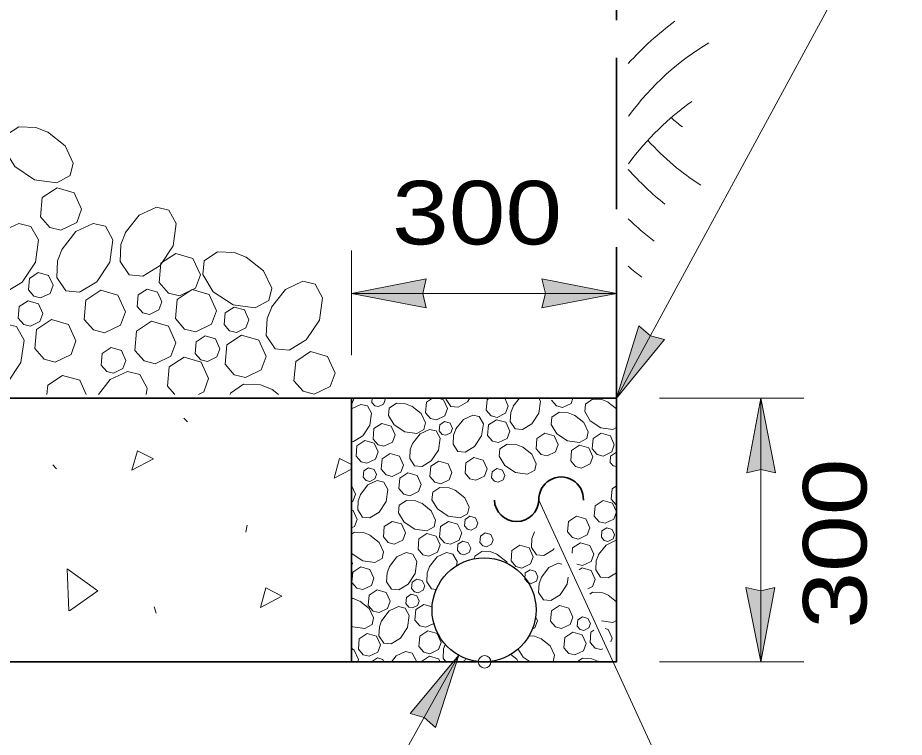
# Model space of a CAD drawing. Extents: x 17672 to 18472, y -9785 to -9267.
# Drawn here: x 18130.28 to 18179.55, y -9409.42 to -9369.46 of the extents above; entities that cross this region are included whole.
import ezdxf

# ---------------------------------------------------------------- set-up
doc = ezdxf.new("R2010")
doc.units = 0
doc.header["$LTSCALE"] = 1.4
doc.header["$PDMODE"] = 32
doc.header["$PDSIZE"] = 0.7
doc.linetypes.add('LONG_DASHED', pattern=[7.5, 6, -1.5])
for name, color, linetype, lineweight in [('1', 7, 'Continuous', 13), ('15', 7, 'Continuous', 13), ('16', 7, 'Continuous', 13)]:
    doc.layers.add(name, color=color, linetype=linetype, lineweight=lineweight)
doc.layers.add('19', color=7, linetype='Continuous')

msp = doc.modelspace()

# ---------------------------------------------------------------- hatches: boundary and pattern name
at = {"layer": '16'}
for points in [[(18148.839, -9384.78), (18152.979, -9385.562), (18152.79, -9384.78), (18152.977, -9383.962)], [(18163.555, -9384.78), (18159.418, -9385.562), (18159.604, -9384.78), (18159.415, -9383.959)], [(18163.555, -9390.594), (18166.217, -9387.329), (18165.44, -9387.121), (18164.808, -9386.567)], [(18171.575, -9390.594), (18170.793, -9394.732), (18171.575, -9394.545), (18172.396, -9394.734)], [(18171.575, -9405.234), (18172.357, -9401.097), (18171.575, -9401.283), (18170.754, -9401.097)], [(18154.79, -9404.869), (18152.092, -9408.102), (18152.866, -9408.32), (18153.491, -9408.884)]]:
    msp.add_hatch(color=256, dxfattribs=at).paths.add_polyline_path(points)

# ---------------------------------------------------------------- linework, layer by layer
at = {"layer": '1', "linetype": 'LONG_DASHED', "lineweight": 35}
msp.add_line((18163.555, -9390.594), (18163.555, -9317.655), dxfattribs=at)
at = {"layer": '1'}
for p, q in [((18139.01, -9390.38), (18138.61, -9389.921)), ((18144.428, -9390.101), (18144.782, -9390.38)), ((18149.962, -9390.82), (18149.984, -9390.594)), ((18157.815, -9391.038), (18158.165, -9390.594)), ((18163.085, -9390.805), (18163.555, -9391.178)), ((18139.511, -9391.705), (18139.719, -9391.906)), ((18132.236, -9394.293), (18132.447, -9394.506)), ((18148.839, -9394.531), (18147.874, -9395.038)), ((18142.952, -9398.028), (18143.038, -9397.633)), ((18163.087, -9401.523), (18163.555, -9401.893)), ((18137.869, -9402.175), (18137.979, -9402.533))]:
    msp.add_line(p, q, dxfattribs=at)
at = {"layer": '1', "lineweight": 25}
msp.add_line((18162.533, -9405.192), (18162.585, -9405.234), dxfattribs=at)
at = {"layer": '1'}
for points in [[(18131.943, -9375.802), (18132.918, -9376.574), (18133.369, -9377.539), (18133.206, -9378.216), (18132.452, -9378.633), (18131.221, -9378.459), (18130.116, -9377.729), (18129.542, -9376.774), (18129.614, -9376.006), (18130.354, -9375.511), (18131.297, -9375.555), (18131.992, -9375.827)], [(18131.552, -9380.519), (18131.647, -9379.448), (18132.474, -9378.906), (18133.423, -9379.179), (18133.835, -9380.092), (18133.561, -9380.835), (18132.682, -9381.261), (18132.063, -9381.106), (18131.553, -9380.518)], [(18136.264, -9381.402), (18137.036, -9380.427), (18138.002, -9379.975), (18138.679, -9380.138), (18139.096, -9380.893), (18138.922, -9382.123), (18138.192, -9383.228), (18137.236, -9383.803), (18136.469, -9383.73), (18135.973, -9382.99), (18136.018, -9382.048), (18136.29, -9381.353)], [(18128.607, -9382.311), (18129.379, -9381.337), (18130.345, -9380.885), (18131.021, -9381.048), (18131.438, -9381.803), (18131.265, -9383.034), (18130.535, -9384.138), (18129.579, -9384.713), (18128.812, -9384.641), (18128.316, -9383.9), (18128.36, -9382.958), (18128.633, -9382.262)], [(18132.745, -9382.307), (18133.517, -9381.332), (18134.483, -9380.88), (18135.16, -9381.044), (18135.577, -9381.798), (18135.403, -9383.029), (18134.674, -9384.133), (18133.718, -9384.708), (18132.95, -9384.636), (18132.455, -9383.895), (18132.498, -9382.953), (18132.771, -9382.258)], [(18138.148, -9384.17), (18138.244, -9383.099), (18139.07, -9382.557), (18140.02, -9382.83), (18140.432, -9383.743), (18140.158, -9384.486), (18139.279, -9384.912), (18138.659, -9384.756), (18138.149, -9384.169)], [(18142.973, -9382.749), (18143.948, -9383.521), (18144.4, -9384.487), (18144.236, -9385.164), (18143.482, -9385.58), (18142.251, -9385.407), (18141.147, -9384.678), (18140.572, -9383.721), (18140.644, -9382.955), (18141.384, -9382.459), (18142.327, -9382.502), (18143.022, -9382.775)], [(18139.047, -9386.169), (18139.143, -9385.099), (18139.969, -9384.557), (18140.918, -9384.83), (18141.33, -9385.742), (18141.056, -9386.486), (18140.177, -9386.912), (18139.558, -9386.756), (18139.048, -9386.169)], [(18144.39, -9385.525), (18145.162, -9384.55), (18146.127, -9384.099), (18146.804, -9384.262), (18147.221, -9385.016), (18147.048, -9386.247), (18146.318, -9387.352), (18145.362, -9387.927), (18144.595, -9387.854), (18144.099, -9387.114), (18144.143, -9386.171), (18144.415, -9385.476)], [(18133.981, -9386.212), (18134.077, -9385.142), (18134.903, -9384.599), (18135.852, -9384.872), (18136.265, -9385.785), (18135.991, -9386.529), (18135.111, -9386.954), (18134.492, -9386.799), (18133.982, -9386.211)], [(18130.308, -9386.143), (18130.366, -9385.501), (18130.861, -9385.176), (18131.431, -9385.34), (18131.678, -9385.887), (18131.514, -9386.334), (18130.986, -9386.589), (18130.615, -9386.496), (18130.309, -9386.143)], [(18141.754, -9386.493), (18141.811, -9385.851), (18142.307, -9385.526), (18142.877, -9385.69), (18143.125, -9386.237), (18142.96, -9386.684), (18142.433, -9386.939), (18142.061, -9386.846), (18141.755, -9386.493)], [(18127.805, -9387.878), (18128.577, -9386.903), (18129.543, -9386.452), (18130.219, -9386.615), (18130.636, -9387.369), (18130.462, -9388.6), (18129.733, -9389.704), (18128.777, -9390.279), (18128.01, -9390.207), (18127.514, -9389.467), (18127.558, -9388.524), (18127.831, -9387.829)], [(18131.238, -9387.837), (18131.334, -9386.767), (18132.16, -9386.224), (18133.109, -9386.497), (18133.522, -9387.411), (18133.247, -9388.154), (18132.368, -9388.58), (18131.749, -9388.424), (18131.239, -9387.837)], [(18140.146, -9388.103), (18140.203, -9387.46), (18140.699, -9387.135), (18141.268, -9387.299), (18141.516, -9387.846), (18141.351, -9388.293), (18140.824, -9388.549), (18140.453, -9388.455), (18140.146, -9388.102)], [(18134.923, -9388.748), (18134.98, -9388.106), (18135.476, -9387.78), (18136.046, -9387.944), (18136.293, -9388.492), (18136.129, -9388.938), (18135.601, -9389.194), (18135.23, -9389.1), (18134.924, -9388.748)], [(18145.635, -9389.617), (18145.731, -9388.548), (18146.557, -9388.005), (18147.506, -9388.278), (18147.918, -9389.191), (18147.644, -9389.935), (18146.765, -9390.36), (18146.147, -9390.204), (18145.636, -9389.618)], [(18138.61, -9389.921), (18138.705, -9388.85), (18139.532, -9388.309), (18140.481, -9388.582), (18140.893, -9389.494), (18140.619, -9390.238), (18140.324, -9390.38)], [(18131.907, -9390.38), (18131.953, -9389.865), (18132.778, -9389.323), (18133.729, -9389.596), (18134.083, -9390.38)], [(18134.769, -9390.38), (18135.42, -9389.558), (18136.386, -9389.106), (18137.063, -9389.27), (18137.48, -9390.024), (18137.429, -9390.38)], [(18142.092, -9390.38), (18142.1, -9390.305), (18142.839, -9389.81), (18143.782, -9389.853), (18144.478, -9390.126)], [(18148.974, -9390.594), (18148.856, -9390.908), (18148.839, -9390.918)], [(18148.839, -9391.173), (18149.354, -9390.932), (18149.719, -9391.021), (18149.945, -9391.425), (18149.849, -9392.089), (18149.457, -9392.685), (18148.942, -9392.994), (18148.839, -9392.984)], [(18150.663, -9390.594), (18150.702, -9390.682), (18150.614, -9390.923), (18150.33, -9391.06), (18150.129, -9391.008), (18149.962, -9390.82)], [(18152.18, -9391.028), (18152.705, -9391.445), (18152.95, -9391.967), (18152.861, -9392.332), (18152.455, -9392.555), (18151.79, -9392.462), (18151.195, -9392.07), (18150.886, -9391.553), (18150.925, -9391.141), (18151.325, -9390.874), (18151.832, -9390.896), (18152.205, -9391.043)], [(18152.945, -9391.396), (18152.996, -9390.817), (18153.339, -9390.594)], [(18153.675, -9390.594), (18153.952, -9390.673), (18154.173, -9391.165), (18154.026, -9391.567), (18153.553, -9391.795), (18153.219, -9391.712), (18152.945, -9391.396)], [(18155.408, -9390.594), (18155.281, -9390.785), (18154.766, -9391.097), (18154.352, -9391.057), (18154.084, -9390.658), (18154.087, -9390.594)], [(18156.31, -9391.256), (18156.364, -9390.678), (18156.491, -9390.594)], [(18157.347, -9390.594), (18157.54, -9391.026), (18157.393, -9391.425), (18156.92, -9391.656), (18156.587, -9391.57), (18156.31, -9391.256)], [(18159.246, -9390.594), (18159.339, -9390.763), (18159.246, -9391.425), (18158.854, -9392.021), (18158.339, -9392.332), (18157.925, -9392.293), (18157.658, -9391.893), (18157.683, -9391.386), (18157.83, -9391.011)], [(18161.136, -9390.594), (18161.033, -9390.879), (18160.558, -9391.109), (18160.224, -9391.023), (18159.95, -9390.707)], [(18163.555, -9392.222), (18163.359, -9392.33), (18162.695, -9392.236), (18162.099, -9391.844), (18161.79, -9391.33), (18161.83, -9390.915), (18162.229, -9390.648), (18162.736, -9390.67), (18163.109, -9390.817)], [(18161.224, -9391.531), (18161.749, -9391.947), (18161.991, -9392.464), (18161.906, -9392.83), (18161.496, -9393.055), (18160.835, -9392.962), (18160.239, -9392.567), (18159.93, -9392.053), (18159.969, -9391.641), (18160.366, -9391.374), (18160.876, -9391.398), (18161.251, -9391.543)], [(18154.633, -9392.293), (18155.05, -9391.768), (18155.57, -9391.526), (18155.935, -9391.614), (18156.16, -9392.018), (18156.065, -9392.682), (18155.673, -9393.278), (18155.158, -9393.587), (18154.744, -9393.548), (18154.477, -9393.148), (18154.501, -9392.641), (18154.648, -9392.266)], [(18152.232, -9393.092), (18152.646, -9392.565), (18153.165, -9392.322), (18153.531, -9392.41), (18153.756, -9392.817), (18153.663, -9393.479), (18153.268, -9394.075), (18152.754, -9394.383), (18152.339, -9394.344), (18152.072, -9393.947), (18152.097, -9393.44), (18152.244, -9393.065)], [(18149.084, -9393.805), (18149.136, -9393.227), (18149.582, -9392.935), (18150.092, -9393.082), (18150.315, -9393.575), (18150.168, -9393.974), (18149.692, -9394.205), (18149.361, -9394.119), (18149.084, -9393.803)], [(18159.087, -9393.401), (18159.138, -9392.825), (18159.585, -9392.531), (18160.097, -9392.68), (18160.317, -9393.17), (18160.17, -9393.57), (18159.697, -9393.8), (18159.364, -9393.717), (18159.089, -9393.401)], [(18162.21, -9393.406), (18162.261, -9392.827), (18162.705, -9392.535), (18163.217, -9392.682), (18163.437, -9393.173), (18163.29, -9393.575), (18162.817, -9393.803), (18162.484, -9393.719), (18162.21, -9393.403)], [(18158.334, -9393.29), (18158.859, -9393.707), (18159.102, -9394.227), (18159.013, -9394.592), (18158.609, -9394.815), (18157.945, -9394.724), (18157.352, -9394.33), (18157.04, -9393.815), (18157.08, -9393.401), (18157.479, -9393.136), (18157.986, -9393.158), (18158.361, -9393.305)], [(18163.202, -9394.153), (18163.232, -9393.807), (18163.499, -9393.631), (18163.555, -9393.648)], [(18147.874, -9395.038), (18148.17, -9393.947), (18148.839, -9394.281)], [(18163.555, -9394.391), (18163.366, -9394.342), (18163.202, -9394.153)], [(18149.332, -9395.935), (18149.746, -9395.41), (18150.266, -9395.168), (18150.631, -9395.256), (18150.856, -9395.663), (18150.761, -9396.325), (18150.371, -9396.92), (18149.854, -9397.229), (18149.442, -9397.19), (18149.175, -9396.793), (18149.197, -9396.283), (18149.344, -9395.908)], [(18148.839, -9395.437), (18149.057, -9395.923), (18148.91, -9396.325), (18148.839, -9396.359)], [(18154.599, -9395.702), (18155.124, -9396.119), (18155.366, -9396.638), (18155.278, -9397.004), (18154.874, -9397.229), (18154.209, -9397.133), (18153.616, -9396.741), (18153.305, -9396.227), (18153.344, -9395.812), (18153.744, -9395.548), (18154.251, -9395.57), (18154.626, -9395.717)], [(18163.266, -9396.192), (18163.317, -9395.616), (18163.555, -9395.459)], [(18152.739, -9396.428), (18153.263, -9396.844), (18153.506, -9397.364), (18153.42, -9397.729), (18153.013, -9397.952), (18152.349, -9397.859), (18151.756, -9397.467), (18151.445, -9396.952), (18151.484, -9396.538), (18151.883, -9396.273), (18152.391, -9396.295), (18152.766, -9396.442)], [(18163.555, -9396.511), (18163.54, -9396.506), (18163.266, -9396.192)], [(18148.839, -9396.808), (18148.92, -9396.83), (18149.141, -9397.322), (18148.994, -9397.722), (18148.839, -9397.798)], [(18148.839, -9398.138), (18148.994, -9398.033), (18149.501, -9398.058), (18149.876, -9398.205)], [(18149.849, -9398.19), (18150.374, -9398.604), (18150.619, -9399.126), (18150.531, -9399.489), (18150.124, -9399.714), (18149.459, -9399.621), (18148.866, -9399.229), (18148.839, -9399.183)], [(18160.089, -9398.935), (18160.033, -9399.018), (18159.518, -9399.33), (18159.104, -9399.29), (18158.837, -9398.891), (18158.861, -9398.384), (18159.009, -9398.008)], [(18161.089, -9399.202), (18161.116, -9398.91), (18161.56, -9398.619), (18162.072, -9398.766), (18162.295, -9399.256), (18162.146, -9399.658), (18161.673, -9399.886), (18161.354, -9399.808)], [(18162.567, -9399.271), (18162.984, -9398.744), (18163.504, -9398.501), (18163.555, -9398.513)], [(18150.942, -9399.935), (18151.356, -9399.41), (18151.879, -9399.168), (18152.244, -9399.254), (18152.467, -9399.66), (18152.374, -9400.325), (18151.982, -9400.918), (18151.467, -9401.229), (18151.053, -9401.19), (18150.785, -9400.79), (18150.81, -9400.283), (18150.957, -9399.908)], [(18153.17, -9399.933), (18153.587, -9399.408), (18154.107, -9399.165), (18154.472, -9399.251), (18154.697, -9399.658), (18154.663, -9399.896)], [(18155.665, -9399.506), (18155.678, -9399.371), (18156.077, -9399.104), (18156.584, -9399.129), (18156.959, -9399.276)], [(18156.933, -9399.263), (18157.457, -9399.678), (18157.499, -9399.766)], [(18163.555, -9400.285), (18163.092, -9400.562), (18162.678, -9400.523), (18162.411, -9400.126), (18162.435, -9399.619), (18162.582, -9399.244)], [(18159.386, -9400.526), (18159.803, -9400.001), (18160.322, -9399.756), (18160.513, -9399.803)], [(18133.131, -9402.398), (18133.035, -9400.06), (18134.741, -9401.281), (18133.163, -9402.393)], [(18153.54, -9401.212), (18153.283, -9401.187), (18153.016, -9400.788), (18153.038, -9400.281), (18153.185, -9399.906)], [(18158.457, -9400.641), (18158.489, -9400.295), (18158.756, -9400.119), (18159.062, -9400.207), (18159.195, -9400.504), (18159.107, -9400.744), (18158.822, -9400.881), (18158.624, -9400.83), (18158.459, -9400.641)], [(18161.491, -9400.116), (18161.646, -9400.016), (18162.156, -9400.163), (18162.379, -9400.656), (18162.232, -9401.055), (18161.96, -9401.187)], [(18160.871, -9400.538), (18160.817, -9400.915), (18160.425, -9401.511), (18159.91, -9401.82), (18159.496, -9401.781), (18159.232, -9401.381), (18159.254, -9400.874), (18159.401, -9400.499)], [(18148.839, -9401.719), (18148.947, -9401.724), (18149.32, -9401.874)], [(18162.082, -9401.467), (18162.232, -9401.366), (18162.739, -9401.391), (18163.114, -9401.538)], [(18149.293, -9401.859), (18149.82, -9402.273), (18150.062, -9402.795), (18149.974, -9403.16), (18149.57, -9403.384), (18148.905, -9403.29), (18148.839, -9403.246)], [(18150.511, -9402.933), (18150.925, -9402.408), (18151.447, -9402.165), (18151.81, -9402.254), (18152.035, -9402.66), (18151.942, -9403.322), (18151.55, -9403.918), (18151.033, -9404.227), (18150.621, -9404.187), (18150.354, -9403.79), (18150.379, -9403.281), (18150.526, -9402.908)], [(18152.359, -9402.91), (18152.41, -9402.335), (18152.857, -9402.043), (18153.312, -9402.175)], [(18159.062, -9402.714), (18159.168, -9402.95), (18159.021, -9403.352), (18158.879, -9403.42)], [(18153.408, -9403.099), (18152.969, -9403.312), (18152.636, -9403.227), (18152.359, -9402.91)], [(18163.555, -9402.942), (18163.361, -9403.048), (18162.734, -9402.96)], [(18149.212, -9404.526), (18149.263, -9403.95), (18149.709, -9403.658), (18150.222, -9403.803), (18150.442, -9404.295), (18150.295, -9404.695), (18149.822, -9404.925), (18149.489, -9404.842), (18149.214, -9404.526)], [(18158.7, -9403.788), (18159.004, -9403.803), (18159.379, -9403.95)], [(18160.634, -9404.452), (18160.687, -9403.876), (18161.131, -9403.582), (18161.643, -9403.732), (18161.866, -9404.222), (18161.717, -9404.621), (18161.244, -9404.852), (18160.91, -9404.768), (18160.636, -9404.452)], [(18162.089, -9404.156), (18162.141, -9403.58), (18162.3, -9403.474)], [(18162.92, -9403.384), (18163.097, -9403.433), (18163.317, -9403.925), (18163.244, -9404.126)], [(18154.067, -9405.234), (18153.928, -9405.023), (18153.95, -9404.516), (18154.045, -9404.273)], [(18159.352, -9403.935), (18159.879, -9404.352), (18160.121, -9404.871), (18160.033, -9405.234)], [(18162.803, -9404.506), (18162.697, -9404.555), (18162.364, -9404.472), (18162.089, -9404.156)], [(18148.839, -9404.469), (18148.974, -9404.577), (18149.217, -9405.097), (18149.182, -9405.234)], [(18151.053, -9405.234), (18151.317, -9404.898), (18151.839, -9404.656), (18152.205, -9404.744), (18152.428, -9405.151), (18152.415, -9405.234)], [(18158.763, -9405.234), (18158.369, -9404.974), (18158.097, -9404.521)], [(18150.001, -9405.234), (18150.004, -9405.192), (18150.271, -9405.018), (18150.577, -9405.107), (18150.636, -9405.234)], [(18152.712, -9405.234), (18152.717, -9405.207), (18153.16, -9404.915), (18153.673, -9405.062), (18153.751, -9405.234)], [(18155.187, -9405.053), (18155.124, -9405.153), (18154.986, -9405.234)], [(18157.692, -9404.817), (18158.018, -9405.077), (18158.092, -9405.234)], [(18161.379, -9405.234), (18161.675, -9405.036), (18162.183, -9405.06), (18162.558, -9405.207)]]:
    msp.add_lwpolyline(points, dxfattribs=at)
for points in [[(18130.876, -9384.577), (18130.933, -9383.935), (18131.429, -9383.61), (18131.999, -9383.774), (18132.246, -9384.321), (18132.082, -9384.768), (18131.554, -9385.023), (18131.183, -9384.93)], [(18136.928, -9385.497), (18136.985, -9384.855), (18137.481, -9384.53), (18138.051, -9384.694), (18138.298, -9385.241), (18138.134, -9385.687), (18137.606, -9385.943), (18137.235, -9385.85)], [(18136.791, -9387.932), (18136.886, -9386.862), (18137.713, -9386.32), (18138.662, -9386.593), (18139.074, -9387.506), (18138.8, -9388.25), (18137.921, -9388.676), (18137.302, -9388.52)], [(18141.805, -9388.698), (18141.9, -9387.628), (18142.727, -9387.086), (18143.676, -9387.359), (18144.088, -9388.271), (18143.814, -9389.015), (18142.935, -9389.441), (18142.316, -9389.285)], [(18153.705, -9392.408), (18153.736, -9392.062), (18154.004, -9391.888), (18154.31, -9391.977), (18154.442, -9392.271), (18154.354, -9392.511), (18154.07, -9392.648), (18153.869, -9392.599)], [(18156.396, -9392.653), (18156.447, -9392.077), (18156.891, -9391.783), (18157.403, -9391.93), (18157.626, -9392.423), (18157.477, -9392.825), (18157.004, -9393.053), (18156.67, -9392.969)], [(18150.028, -9392.859), (18150.08, -9392.281), (18150.526, -9391.989), (18151.038, -9392.136), (18151.258, -9392.629), (18151.111, -9393.028), (18150.638, -9393.258), (18150.305, -9393.173)], [(18161.013, -9394.07), (18161.065, -9393.494), (18161.511, -9393.202), (18162.021, -9393.349), (18162.241, -9393.842), (18162.097, -9394.241), (18161.621, -9394.472), (18161.288, -9394.386)], [(18136.626, -9394.587), (18136.94, -9393.511), (18137.834, -9393.964)], [(18150.484, -9394.535), (18150.535, -9393.959), (18150.981, -9393.668), (18151.491, -9393.812), (18151.714, -9394.305), (18151.567, -9394.707), (18151.094, -9394.935), (18150.761, -9394.852)], [(18155.141, -9394.749), (18155.192, -9394.173), (18155.638, -9393.881), (18156.148, -9394.028), (18156.371, -9394.518), (18156.224, -9394.92), (18155.749, -9395.148), (18155.415, -9395.065)], [(18153.187, -9394.947), (18153.236, -9394.371), (18153.682, -9394.08), (18154.195, -9394.227), (18154.415, -9394.717), (18154.268, -9395.119), (18153.795, -9395.349), (18153.462, -9395.263)], [(18149.479, -9394.974), (18149.511, -9394.629), (18149.776, -9394.455), (18150.084, -9394.543), (18150.217, -9394.837), (18150.129, -9395.077), (18149.844, -9395.214), (18149.643, -9395.165)], [(18151.464, -9395.607), (18151.516, -9395.031), (18151.962, -9394.739), (18152.474, -9394.883), (18152.695, -9395.376), (18152.548, -9395.776), (18152.075, -9396.006), (18151.741, -9395.923)], [(18156.616, -9395.016), (18156.648, -9394.673), (18156.915, -9394.496), (18157.222, -9394.584), (18157.354, -9394.879), (18157.266, -9395.119), (18156.982, -9395.258), (18156.781, -9395.207)], [(18162.322, -9397.138), (18162.374, -9396.56), (18162.817, -9396.271), (18163.33, -9396.415), (18163.553, -9396.908), (18163.403, -9397.308), (18162.93, -9397.538), (18162.597, -9397.455)], [(18155.109, -9397.673), (18155.141, -9397.325), (18155.408, -9397.151), (18155.714, -9397.239), (18155.847, -9397.533), (18155.758, -9397.773), (18155.474, -9397.913), (18155.273, -9397.861)], [(18160.844, -9398.013), (18160.896, -9397.437), (18161.342, -9397.143), (18161.852, -9397.293), (18162.075, -9397.783), (18161.928, -9398.185), (18161.452, -9398.413), (18161.119, -9398.33)], [(18150.604, -9398.298), (18150.656, -9397.722), (18151.099, -9397.43), (18151.611, -9397.577), (18151.832, -9398.067), (18151.685, -9398.469), (18151.212, -9398.7), (18150.879, -9398.614)], [(18153.724, -9398.303), (18153.776, -9397.724), (18154.222, -9397.435), (18154.732, -9397.58), (18154.955, -9398.072), (18154.808, -9398.472), (18154.332, -9398.702), (18153.999, -9398.619)], [(18162.717, -9398.308), (18162.746, -9397.962), (18163.013, -9397.788), (18163.32, -9397.876), (18163.455, -9398.17), (18163.366, -9398.41), (18163.082, -9398.548), (18162.881, -9398.499)], [(18152.528, -9398.969), (18152.58, -9398.393), (18153.026, -9398.102), (18153.535, -9398.249), (18153.758, -9398.739), (18153.611, -9399.141), (18153.138, -9399.369), (18152.803, -9399.285)], [(18155.969, -9398.599), (18155.999, -9398.254), (18156.266, -9398.077), (18156.575, -9398.165), (18156.707, -9398.462), (18156.619, -9398.702), (18156.334, -9398.839), (18156.136, -9398.788)], [(18154.717, -9399.053), (18154.746, -9398.705), (18155.013, -9398.531), (18155.322, -9398.619), (18155.455, -9398.913), (18155.366, -9399.156), (18155.082, -9399.293), (18154.881, -9399.241)], [(18157.697, -9399.626), (18157.749, -9399.05), (18158.195, -9398.759), (18158.705, -9398.906), (18158.928, -9399.398), (18158.778, -9399.798), (18158.305, -9400.028), (18157.972, -9399.942)], [(18148.852, -9400.82), (18148.903, -9400.244), (18149.347, -9399.955), (18149.859, -9400.099), (18150.082, -9400.592), (18149.935, -9400.991), (18149.459, -9401.222), (18149.126, -9401.136)], [(18152.165, -9401.156), (18152.195, -9400.81), (18152.462, -9400.634), (18152.768, -9400.722), (18152.903, -9401.018), (18152.815, -9401.259), (18152.531, -9401.396), (18152.33, -9401.347)], [(18143.768, -9402.219), (18144.065, -9401.131), (18144.962, -9401.585)], [(18149.758, -9402.097), (18149.81, -9401.521), (18150.256, -9401.229), (18150.766, -9401.376), (18150.989, -9401.866), (18150.842, -9402.266), (18150.369, -9402.496), (18150.033, -9402.413)], [(18151.859, -9401.999), (18151.888, -9401.653), (18152.156, -9401.479), (18152.462, -9401.567), (18152.597, -9401.861), (18152.508, -9402.102), (18152.224, -9402.239), (18152.023, -9402.19)], [(18159.893, -9402.982), (18159.945, -9402.403), (18160.391, -9402.111), (18160.903, -9402.259), (18161.124, -9402.751), (18160.977, -9403.153), (18160.504, -9403.381), (18160.17, -9403.298)], [(18161.369, -9403.249), (18161.401, -9402.903), (18161.668, -9402.729), (18161.974, -9402.817), (18162.107, -9403.111), (18162.018, -9403.352), (18161.734, -9403.489), (18161.535, -9403.44)], [(18152.58, -9404.386), (18152.631, -9403.808), (18153.077, -9403.516), (18153.587, -9403.663), (18153.81, -9404.156), (18153.663, -9404.555), (18153.19, -9404.786), (18152.854, -9404.702)]]:
    msp.add_lwpolyline(points, close=True, dxfattribs=at)
at = {"layer": '1', "lineweight": 35}
for points in [[(18095.915, -9390.594), (18057.336, -9390.594), (18057.336, -9405.234), (18148.839, -9405.234), (18148.839, -9390.594), (18120.263, -9390.594)], [(18148.839, -9405.234), (18163.555, -9405.234), (18163.555, -9390.594), (18148.839, -9390.594)]]:
    msp.add_lwpolyline(points, close=True, dxfattribs=at)
at = {"layer": '1', "lineweight": 25}
for points in [[(18120.263, -9390.594), (18148.839, -9390.594), (18120.263, -9390.594)], [(18148.839, -9399.707), (18148.871, -9399.778), (18148.839, -9399.864)]]:
    msp.add_lwpolyline(points, dxfattribs=at)
msp.add_circle((18156.198, -9402.346), 2.889, dxfattribs=at)
at = {"layer": '1'}
for centre, major_axis, start_param, end_param in [((18174.22, -9389.391), (0, 22.266), 0.481461, 0.675019), ((18174.22, -9389.391), (0, 20.062), 0.393014, 0.765516), ((18174.22, -9392.041), (0, 20.062), 0.464937, 0.765516), ((18174.29, -9358.036), (0, -20.062), 5.720851, 5.771052), ((18174.22, -9360.5), (0, -20.062), 5.616853, 5.85583), ((18174.22, -9360.5), (0, -22.266), 5.608166, 5.761688), ((18174.22, -9360.5), (0, -24.471), 5.678359, 5.774233), ((18174.22, -9360.5), (0, -26.675), 5.734425, 5.779681)]:
    msp.add_ellipse(centre, major_axis=major_axis, ratio=0.719298, start_param=start_param, end_param=end_param, dxfattribs=at)
msp.add_point((18156.229, -9405.234), dxfattribs=at)
at = {"layer": '15'}
for p, q in [((18179.55, -9361.099), (18163.555, -9390.594)), ((18148.839, -9388.197), (18148.839, -9382.383)), ((18163.555, -9384.78), (18148.839, -9384.78)), ((18165.952, -9390.594), (18173.969, -9390.594)), ((18171.575, -9405.234), (18171.575, -9390.594)), ((18167.411, -9414.021), (18159.246, -9396.251)), ((18165.952, -9405.234), (18173.969, -9405.234))]:
    msp.add_line(p, q, dxfattribs=at)
msp.add_lwpolyline([(18137.415, -9422.389), (18145.021, -9422.389), (18154.79, -9404.869)], dxfattribs=at)
at = {"layer": '16'}
for points in [[(18148.839, -9384.78), (18152.979, -9385.562), (18152.79, -9384.78), (18152.977, -9383.962)], [(18163.555, -9384.78), (18159.418, -9385.562), (18159.604, -9384.78), (18159.415, -9383.959)], [(18163.555, -9390.594), (18166.217, -9387.329), (18165.44, -9387.121), (18164.808, -9386.567)], [(18171.575, -9390.594), (18170.793, -9394.732), (18171.575, -9394.545), (18172.396, -9394.734)], [(18171.575, -9405.234), (18172.357, -9401.097), (18171.575, -9401.283), (18170.754, -9401.097)], [(18154.79, -9404.869), (18152.092, -9408.102), (18152.866, -9408.32), (18153.491, -9408.884)]]:
    msp.add_lwpolyline(points, close=True, dxfattribs=at)
at = {"layer": '16', "lineweight": 35}
for centre, start, end in [((18160.483, -9396.204), 357.8424, 182.1576), ((18158.009, -9396.204), 182.1576, 357.8424)]:
    msp.add_arc(centre, 1.238, start, end, dxfattribs=at)

# ---------------------------------------------------------------- texts
at = {"layer": '19', "width": 1.2}
msp.add_text('300', height=3.529, dxfattribs=at).set_placement((18151.089, -9382.048))
msp.add_text('300', height=3.529, rotation=90, dxfattribs=at).set_placement((18177.452, -9403.388))

doc.saveas('drawing.dxf')
